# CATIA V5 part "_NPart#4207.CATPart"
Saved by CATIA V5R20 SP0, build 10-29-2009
Part number: DIN6325 Ø2,5X20_Parallel Pin ISO 2338 - 2.5 h6 x 20 - St
Revision: ANY
Definition: UNKNOWN
Nomenclature: DIN6325 Ø2,5X20_Parallel Pin ISO 2338 - 2.5 h6 x 20 - St
Source: Unknown
Bounding box of the stored display mesh (mm): x 0 to 20, y -1.25 to 1.25, z -1.25 to 1.25
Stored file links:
  C:\Users\Utente\Desktop\IO LAVORO\3D X SITO CF\CUMSA\3D files AE\AE 041620\_NPart#4207.CATPart
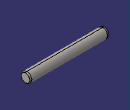
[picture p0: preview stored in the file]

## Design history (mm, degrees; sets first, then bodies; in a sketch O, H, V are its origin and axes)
Body1 "Base-Revolve" (main body)
  Solid1: solid without history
